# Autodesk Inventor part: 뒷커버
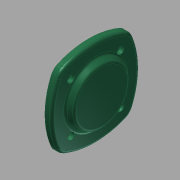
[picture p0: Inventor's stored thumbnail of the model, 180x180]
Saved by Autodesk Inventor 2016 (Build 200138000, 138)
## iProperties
Created: 2015-11
Part Number: 뒷커버
Material: 일반
Document SubType Name: Modeling
Designer: mduedu
Density: 1 g/cm^3
Appearance: 매끄러움 - 짙은 바다 녹색
Mass: 120.055 g
Surface Area: 247.582 cm^2
Volume: 120.055 cm^3
Author: mduedu
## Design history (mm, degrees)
sketch "스케치1"
  geometry: L1 (50, 50)-(-50, 50); L2 (-50, 50)-(-50, -50); L3 (-50, -50)-(50, -50); L4 (50, -50)-(50, 50); L5 (0, 50)-(0, -50); L6 (50, 0)-(-50, 0); A1 r 90 centre (-40, 0) between (40.415, -40.415) and (40.415, 40.415); A2 r 90 centre (40, 0) between (-40.415, 40.415) and (-40.415, -40.415); A3 r 90 centre (0, -40) between (40.415, 40.415) and (-40.415, 40.415); A4 r 90 centre (0, 40) between (-40.415, -40.415) and (40.415, -40.415); 2 further points
  constraints: 12 end point, 8 point on circle, 5 midpoint, 4 centre point, 2 horizontal alignment, 2 parallel, 2 perpendicular, 2 symmetric about line, 2 tangent, 2 vertical alignment, 1 equal radius, 1 horizontal, 2 other
  dimensions: "d0" = 100 distance of L3.end L1.start; "d2" = 90 radius of A1
extrude "돌출1" new body sketch "스케치1" distance "d3" = 8; taper "d4" = 0 deg
sketch "스케치2"
  geometry: C1 r 35 at (0, 0); 1 further point
  constraints: 1 centre point, 1 coincident
  dimensions: "d5" = 70 diameter of C1
extrude "돌출2" join sketch "스케치2" distance "d6" = 7; taper "d7" = -30 deg
sketch "스케치3"
  geometry: L1 (0, 0)-(0, 40); L2 (0, 0)-(-28.284, 28.284); A1 r 40 centre (0, 0) between (0, 40) and (-28.284, 28.284); 2 further points
  constraints: 4 end point, 2 coincident, 2 point on circle, 1 centre point, 1 vertical
  dimensions: "d8" = 80 diameter of A1; "d9" = 45 deg angle of L1 L2
hole "구멍1" sketch "스케치3" at (-28.284, 28.284) diameter "d11" = 4.5; stored, may be unused: countersink angle "d15" = 90 deg, drill point angle "d17" = 118 deg; dims "d12" = 6, "d13" = 8, "d14" = 4.4, "d16" = 8
sketch "스케치4"
  geometry: C1 r 35 at (0, 0); 1 further point
  constraints: 1 centre point, 1 coincident
  dimensions: "d21" = 70 diameter of C1
extrude "돌출3" join sketch "스케치4" distance "d23" = 12; taper "d24" = 0 deg
hole "구멍2" diameter "d27" = 30; stored, may be unused: countersink angle "d31" = 90 deg, drill point angle "d33" = 0 deg; dims "d25" = 10, "d26" = 10, "d28" = 6, "d29" = 40, "d30" = 12, "d32" = 15
fillet "모깎기2" dims "d35" = 15
fillet "모깎기3" dims "d36" = 3
fillet "모깎기4" dims "d37" = 3
fillet "모깎기5" dims "d38" = 0.3
chamfer "모따기1" distance "d39" = 1; stored, may be unused: second distance "d40" = 2, angle "d41" = 45 deg
node "솔리드1"
pattern_circular "원형 패턴1" dims angle "d19" = 360 deg
